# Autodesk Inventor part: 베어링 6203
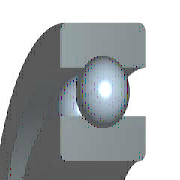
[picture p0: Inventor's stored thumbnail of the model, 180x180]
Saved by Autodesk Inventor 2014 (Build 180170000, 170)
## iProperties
IsCustomPart: 0
Created: 2016-04
Part Number: 베어링 6203
Material: 알루미늄 6061
Description: 깊은 그루브 볼 베어링
Document SubType Name: Modeling
Standard: KS B 2023
Designer: mdu
Standards Organization: KS
Language: ko-KR
Size Designation: 6203 - 17 x 40 x 12
Categories: <MemberInstance><Categories><Category DisplayName="샤프트 부품" InternalName="7f7aeb1f-a693-4053-b835-cee3144e0d98" Mnemonic="SHFT"><Category DisplayName="베어링" Inter
Density: 2.71 g/cm^3
Mass: 22.4044 g
Surface Area: 64.3582 cm^2
Volume: 8.26729 cm^3
Appearance: 알루미늄 - 평지
Author: mdu
Revision Number: 1
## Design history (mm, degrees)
sketch "스케치" dims "d0" = 5.98 (= -0.26 x WD + 0.26 x BD)
  geometry: L1 (3.01, 14.25)-(8.99, 14.25); L2 (6, 14.25)-(6, 11.26); L3 (6, 14.25)-(6, 17.24); L4 (3.778, 12.249)-(0, 12.249); L5 (0, 8.5)-(12, 8.5); L6 (3.778, 16.251)-(0, 16.251); L7 (0, 20)-(12, 20); L8 (12, 8.5)-(12, 12.249); L9 (8.222, 12.249)-(12, 12.249); L10 (8.222, 16.251)-(12, 16.251); L11 (12, 20)-(12, 16.251); L12 (-1.4, 0)-(8.4, 0) reference; L13 (0, -0.3)-(0, 5.3) reference
  constraints: 22 end point, 4 point on line, 2 collinear, 2 perpendicular, 2 symmetric about line, 1 midpoint, 1 parallel, 14 other
  dimensions: "d9" = 17 diameter of L5 L12 (= WD); "d11" = 40 diameter of L7 L12 (= BD); "d12" = 12 distance between parallel lines of L8 L13 (= KB); "d13" = 24.498 diameter of L9 L12 (= 0.326 x BD + 0.674 x WD)
revolve "본체" stored, may be unused: angle "d6" = 90 deg
revolve "볼" stored, may be unused: angle "d7" = 90 deg
pattern_circular "IDS_ARRAYBALL[SIMPL:T]" dims angle "d3" = 360 deg
body "Solid1"
fillet "모깎기1" dims "d1" = 0.6 (= KRS)
other parameters: "WD" = 17 [user parameter; used in 5 equation terms], "BD" = 40 [user parameter; used in 5 equation terms], "KB" = 12 [user parameter; used in 1 equation term], "KRS" = 0.6 [user parameter; used in 1 equation term], "d4" = 0, "d5" = 0, "d8" = 0, "d14" = 0, "d15" = 0, "BBA" = 0 [user parameter], "BC0" = 4750000 [user parameter], "BC" = 9560000 [user parameter], "WR" = 8.5 (= 0.5 x WD) [user parameter]
